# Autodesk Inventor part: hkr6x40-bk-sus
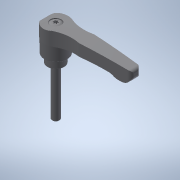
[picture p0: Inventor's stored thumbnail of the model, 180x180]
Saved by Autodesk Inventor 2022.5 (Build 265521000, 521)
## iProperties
Created: 2017-09
Part Number: hkr6x40-bk-sus
Material: 一般
Document SubType Name: Modeling
Designer: imaocorp
Density: 1 g/cm^3
Appearance: 既定
Author: imaocorp
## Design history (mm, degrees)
node "hkr6x40-bk-sus.x_t1"
node "hkr6x40-bk-sus"
node "Base1"
